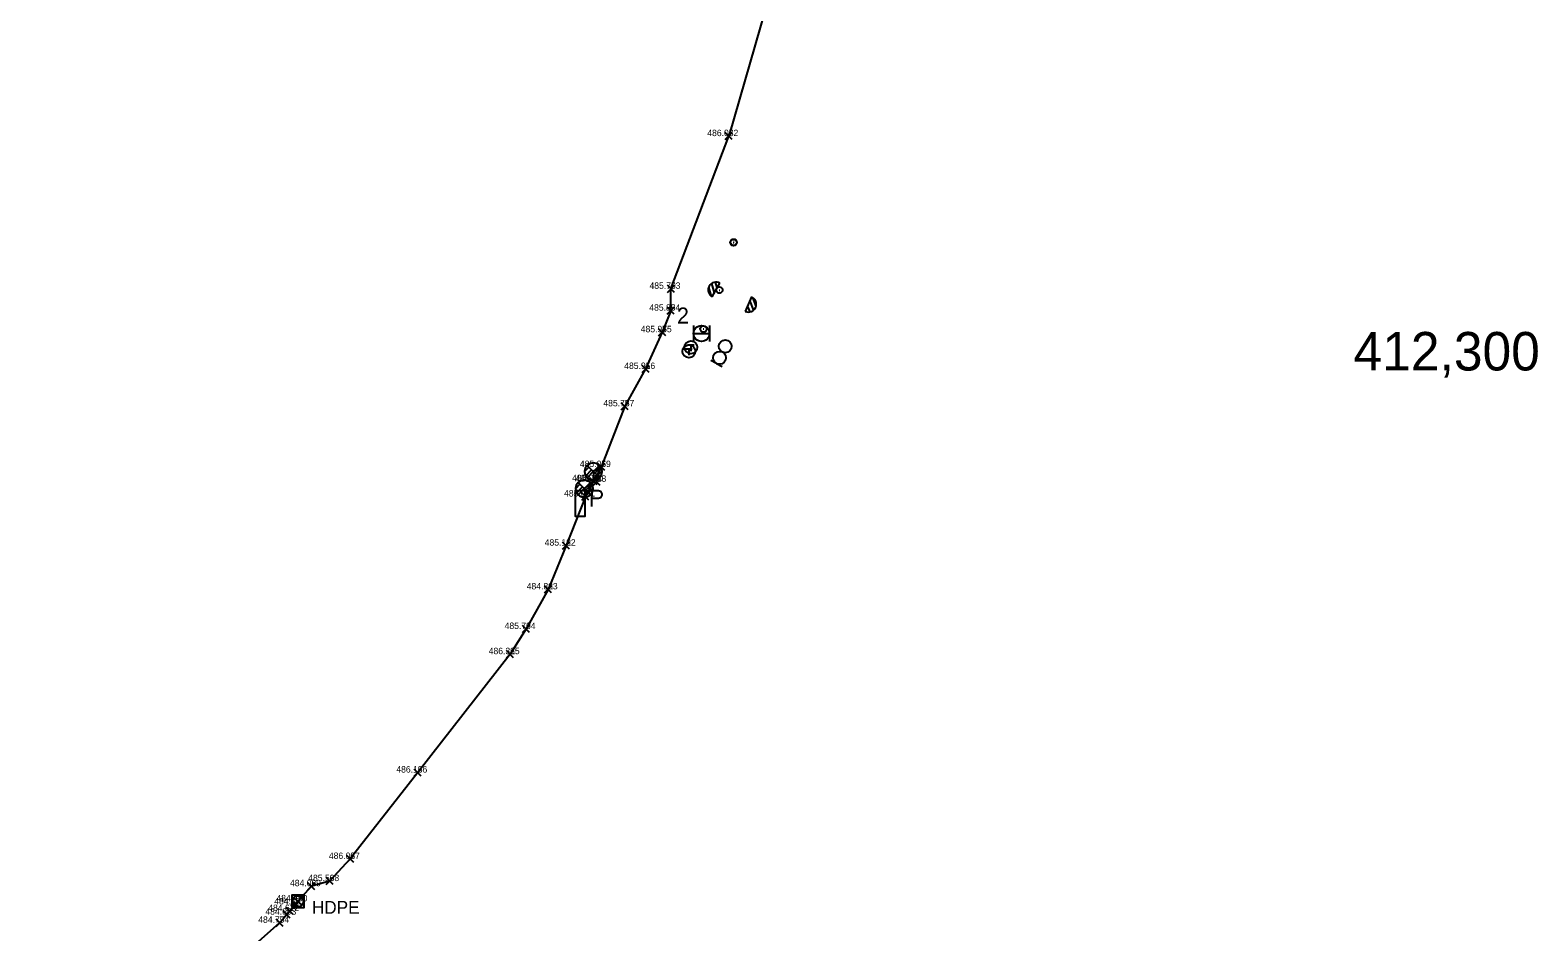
# Model space of a CAD drawing. Extents: x -874058 to -854960, y -10531873 to -1049126.
# Drawn here: x -866673.8 to -866439.1, y -1050448 to -1050307.6 of the extents above; entities that cross this region are included whole.
import ezdxf

# ---------------------------------------------------------------- set-up
doc = ezdxf.new("R2010")
doc.units = 0
for name, color, linetype in [('Vrstva 2', 7, 'Continuous'), ('Vrstva 3', 7, 'Continuous'), ('Vrstva 30', 7, 'Continuous'), ('Vrstva 31', 7, 'Continuous'), ('Vrstva 32', 7, 'Continuous'), ('Vrstva 33', 7, 'Continuous'), ('Vrstva 50', 7, 'Continuous'), ('Vrstva 6', 7, 'Continuous'), ('Vrstva 60', 7, 'Continuous'), ('Vrstva 61', 7, 'Continuous'), ('Vrstva 7', 7, 'Continuous')]:
    doc.layers.add(name, color=color, linetype=linetype)

msp = doc.modelspace()

# ---------------------------------------------------------------- linework, layer by layer
at = {"layer": 'Vrstva 3'}
for p, q in [((-866567.7, -1050349.03), (-866568.11, -1050347.61)), ((-866567.21, -1050348.48), (-866567.63, -1050347.01)), ((-866567.56, -1050349.12), (-866566.37, -1050346.96)), ((-866566.79, -1050347.72), (-866567.05, -1050346.81)), ((-866566.37, -1050346.96), (-866566.37, -1050346.96)), ((-866566.37, -1050346.96), (-866566.37, -1050346.96)), ((-866561.45, -1050349.11), (-866562.42, -1050351.38)), ((-866561.74, -1050349.78), (-866561.17, -1050351.21)), ((-866561.31, -1050349.19), (-866560.76, -1050350.56)), ((-866562.42, -1050351.38), (-866562.42, -1050351.38)), ((-866562.42, -1050351.38), (-866562.42, -1050351.38)), ((-866562.08, -1050350.59), (-866561.73, -1050351.46)), ((-866570.48, -1050353.59), (-866570.48, -1050356.05)), ((-866568.02, -1050353.59), (-866568.02, -1050356.05)), ((-866571.4, -1050356.56), (-866570.4, -1050356.56)), ((-866570.9, -1050356.56), (-866570.9, -1050357.56)), ((-866570.48, -1050354.82), (-866568.02, -1050354.82)), ((-866571.71, -1050357.2), (-866570.71, -1050357.2)), ((-866571.21, -1050357.2), (-866571.21, -1050358.2))]:
    msp.add_line(p, q, dxfattribs=at)
for centre, radius in [((-866569.25, -1050354.82), 1.23), ((-866571.21, -1050357.6), 1), ((-866570.9, -1050356.96), 1)]:
    msp.add_circle(centre, radius, dxfattribs=at)
for centre, start, end in [((-866566.96, -1050348.04), 150.9842, 240.9842), ((-866566.96, -1050348.04), 60.9842, 150.9784), ((-866561.94, -1050350.25), 336.7737, 66.7737), ((-866561.94, -1050350.25), 246.7737, 336.7679)]:
    msp.add_arc(centre, 1.23, start, end, dxfattribs=at)
at = {"layer": 'Vrstva 30'}
msp.add_lwpolyline([(-866633.04, -1050444.23), (-866631.12, -1050444.23), (-866631.12, -1050442.31), (-866633.04, -1050442.31)], close=True, dxfattribs=at)
msp.add_circle((-866632.08, -1050443.27), 0.864, dxfattribs=at)
at = {"layer": 'Vrstva 31'}
for p, q in [((-866587.44, -1050376.33), (-866586.76, -1050375.66)), ((-866585.86, -1050376.55), (-866584.94, -1050375.63)), ((-866585.13, -1050375.37), (-866585.13, -1050375.37)), ((-866585.13, -1050375.37), (-866585.13, -1050375.37)), ((-866587.27, -1050376.98), (-866586.36, -1050376.06)), ((-866587.26, -1050379.2), (-866586.34, -1050378.28)), ((-866587.05, -1050377.28), (-866587.05, -1050377.28)), ((-866587.05, -1050377.28), (-866587.05, -1050377.28)), ((-866586.53, -1050378.02), (-866586.53, -1050378.02)), ((-866586.53, -1050378.02), (-866586.53, -1050378.02)), ((-866585.45, -1050376.96), (-866584.74, -1050376.25)), ((-866585.12, -1050377.28), (-866585.12, -1050377.28)), ((-866588.83, -1050378.98), (-866588.16, -1050378.31)), ((-866588.67, -1050379.63), (-866587.76, -1050378.71)), ((-866588.45, -1050379.93), (-866588.45, -1050379.93)), ((-866588.45, -1050379.93), (-866588.45, -1050379.93)), ((-866586.85, -1050379.6), (-866586.14, -1050378.9)), ((-866586.53, -1050379.93), (-866586.53, -1050379.93))]:
    msp.add_line(p, q, dxfattribs=at)
for points in [[(-866587.04, -1050375.37), (-866586.09, -1050376.33), (-866587.05, -1050377.28)], [(-866585.13, -1050375.37), (-866586.08, -1050376.33), (-866585.12, -1050377.28)], [(-866588.44, -1050378.02), (-866587.49, -1050378.98), (-866588.45, -1050379.93)], [(-866586.53, -1050378.02), (-866587.48, -1050378.98), (-866586.53, -1050379.93)]]:
    msp.add_lwpolyline(points, dxfattribs=at)
for centre, start, end in [((-866586.09, -1050376.33), 134.5239, 224.7609), ((-866586.08, -1050376.33), 45.4761, 134.8422), ((-866586.08, -1050376.33), 315.2391, 45.4761), ((-866587.49, -1050378.98), 134.5239, 224.7609), ((-866587.48, -1050378.98), 45.4761, 134.8422), ((-866586.09, -1050376.33), 224.7623, 315.5517), ((-866587.48, -1050378.98), 315.2391, 45.4761), ((-866587.49, -1050378.98), 224.7623, 315.5517)]:
    msp.add_arc(centre, 1.35, start, end, dxfattribs=at)
at = {"layer": 'Vrstva 32'}
for points in [[(-866550.16, -1050258.3), (-866551.67, -1050267.94), (-866551.95, -1050270.2), (-866553.16, -1050280.04), (-866558.06, -1050297.61), (-866559.25, -1050304.08), (-866565.01, -1050324.07)], [(-866574.04, -1050351.27), (-866574.01, -1050347.86), (-866565.01, -1050324.07)], [(-866574.04, -1050351.27), (-866575.37, -1050354.62), (-866577.94, -1050360.34), (-866581.19, -1050366.16), (-866584.85, -1050375.62)], [(-866584.85, -1050375.62), (-866586.06, -1050377.83), (-866587.31, -1050380.21), (-866590.32, -1050387.86), (-866593.12, -1050394.68), (-866596.56, -1050400.84), (-866599.04, -1050404.77), (-866613.42, -1050423.21), (-866623.92, -1050436.67), (-866627.13, -1050440.12), (-866629.97, -1050440.92), (-866632.08, -1050443.27)], [(-866584.85, -1050375.62), (-866586.05, -1050376.28), (-866586.06, -1050377.83), (-866587.46, -1050378.89), (-866587.31, -1050380.21)], [(-866673.75, -1050481.26), (-866665.49, -1050475.11), (-866653.83, -1050464.38), (-866638.62, -1050449.9), (-866634.91, -1050446.62), (-866633.81, -1050445.36), (-866633.36, -1050444.78), (-866632.42, -1050443.75), (-866632.08, -1050443.27)]]:
    msp.add_lwpolyline(points, dxfattribs=at)
at = {"layer": 'Vrstva 33'}
msp.add_lwpolyline([(-866588.87, -1050379.28), (-866587.38, -1050379.28), (-866587.38, -1050383.31), (-866588.87, -1050383.31)], close=True, dxfattribs=at)
for points in [[(-866586.33, -1050381.78), (-866586.33, -1050379.27)], [(-866586.33, -1050379.27), (-866585.29, -1050379.27)], [(-866585.29, -1050380.51), (-866586.33, -1050380.51)], [(-866585.29, -1050379.27), (-866584.97, -1050379.37), (-866584.75, -1050379.78), (-866584.75, -1050380), (-866584.97, -1050380.42), (-866585.29, -1050380.51)]]:
    msp.add_lwpolyline(points, dxfattribs=at)
at = {"layer": 'Vrstva 50'}
for p, q in [((-866566.51, -1050348.05), (-866566.41, -1050348.05)), ((-866568.98, -1050354.11), (-866568.88, -1050354.11))]:
    msp.add_line(p, q, dxfattribs=at)
for centre in [(-866566.46, -1050348.05), (-866568.93, -1050354.11)]:
    msp.add_circle(centre, 0.5, dxfattribs=at)
at = {"layer": 'Vrstva 6'}
for q in [(-866567.78, -1050359.04), (-866566, -1050359.94)]:
    msp.add_line((-866566.89, -1050359.49), q, dxfattribs=at)
for centre in [(-866565.55, -1050356.81), (-866566.44, -1050358.6)]:
    msp.add_circle(centre, 1, dxfattribs=at)
at = {"layer": 'Vrstva 60'}
for p, q in [((-866565.56, -1050324.62), (-866564.46, -1050323.52)), ((-866564.46, -1050324.62), (-866565.56, -1050323.52)), ((-866574.56, -1050348.41), (-866573.46, -1050347.31)), ((-866573.46, -1050348.41), (-866574.56, -1050347.31)), ((-866574.59, -1050351.82), (-866573.49, -1050350.72)), ((-866573.49, -1050351.82), (-866574.59, -1050350.72)), ((-866575.92, -1050355.17), (-866574.82, -1050354.07)), ((-866574.82, -1050355.17), (-866575.92, -1050354.07)), ((-866578.49, -1050360.89), (-866577.39, -1050359.79)), ((-866577.39, -1050360.89), (-866578.49, -1050359.79)), ((-866581.74, -1050366.71), (-866580.64, -1050365.61)), ((-866580.64, -1050366.71), (-866581.74, -1050365.61)), ((-866585.4, -1050376.17), (-866584.3, -1050375.07)), ((-866584.3, -1050376.17), (-866585.4, -1050375.07)), ((-866586.61, -1050378.38), (-866585.51, -1050377.28)), ((-866585.51, -1050378.38), (-866586.61, -1050377.28)), ((-866586.11, -1050378.47), (-866585.01, -1050377.37)), ((-866585.01, -1050378.47), (-866586.11, -1050377.37)), ((-866587.86, -1050380.76), (-866586.76, -1050379.66)), ((-866586.76, -1050380.76), (-866587.86, -1050379.66)), ((-866590.87, -1050388.41), (-866589.77, -1050387.31)), ((-866589.77, -1050388.41), (-866590.87, -1050387.31)), ((-866593.67, -1050395.23), (-866592.57, -1050394.13)), ((-866592.57, -1050395.23), (-866593.67, -1050394.13)), ((-866597.11, -1050401.39), (-866596.01, -1050400.29)), ((-866596.01, -1050401.39), (-866597.11, -1050400.29)), ((-866599.59, -1050405.32), (-866598.49, -1050404.22)), ((-866598.49, -1050405.32), (-866599.59, -1050404.22)), ((-866613.97, -1050423.76), (-866612.87, -1050422.66)), ((-866612.87, -1050423.76), (-866613.97, -1050422.66)), ((-866624.47, -1050437.22), (-866623.37, -1050436.12)), ((-866623.37, -1050437.22), (-866624.47, -1050436.12)), ((-866630.52, -1050441.47), (-866629.42, -1050440.37)), ((-866629.42, -1050441.47), (-866630.52, -1050440.37)), ((-866627.68, -1050440.67), (-866626.58, -1050439.57)), ((-866626.58, -1050440.67), (-866627.68, -1050439.57)), ((-866632.97, -1050444.3), (-866631.87, -1050443.2)), ((-866631.87, -1050444.3), (-866632.97, -1050443.2)), ((-866632.63, -1050443.82), (-866631.53, -1050442.72)), ((-866631.53, -1050443.82), (-866632.63, -1050442.72)), ((-866635.46, -1050447.17), (-866634.36, -1050446.07)), ((-866634.36, -1050447.17), (-866635.46, -1050446.07)), ((-866634.36, -1050445.91), (-866633.26, -1050444.81)), ((-866633.26, -1050445.91), (-866634.36, -1050444.81)), ((-866633.91, -1050445.33), (-866632.81, -1050444.23)), ((-866632.81, -1050445.33), (-866633.91, -1050444.23))]:
    msp.add_line(p, q, dxfattribs=at)
at = {"layer": 'Vrstva 7'}
for p, q in [((-866564.31, -1050340.65), (-866564.21, -1050340.65)), ((-866564.28, -1050340.6), (-866564.18, -1050340.6))]:
    msp.add_line(p, q, dxfattribs=at)
for centre in [(-866564.26, -1050340.65), (-866564.23, -1050340.6)]:
    msp.add_circle(centre, 0.5, dxfattribs=at)

# ---------------------------------------------------------------- texts
at = {"layer": 'Vrstva 2'}
msp.add_text('2', height=2.5, dxfattribs=at).set_placement((-866573.06, -1050353.27))
at = {"layer": 'Vrstva 32'}
msp.add_text('HDPE', height=2, dxfattribs=at).set_placement((-866629.9, -1050445.21))
at = {"layer": 'Vrstva 60'}
for s, p in [('52', (-866565.01, -1050324.07)), ('53', (-866574.01, -1050347.86)), ('54', (-866574.04, -1050351.27)), ('55', (-866575.37, -1050354.62)), ('56', (-866577.94, -1050360.34)), ('57', (-866581.19, -1050366.16)), ('59', (-866584.85, -1050375.62)), ('60', (-866586.06, -1050377.83)), ('58', (-866585.56, -1050377.92)), ('61', (-866587.31, -1050380.21)), ('62', (-866590.32, -1050387.86)), ('63', (-866593.12, -1050394.68)), ('64', (-866596.56, -1050400.84)), ('65', (-866599.04, -1050404.77)), ('66', (-866613.42, -1050423.21)), ('67', (-866623.92, -1050436.67)), ('68', (-866627.13, -1050440.12)), ('69', (-866629.97, -1050440.92)), ('72', (-866633.36, -1050444.78)), ('71', (-866632.42, -1050443.75)), ('70', (-866632.08, -1050443.27)), ('74', (-866634.91, -1050446.62)), ('73', (-866633.81, -1050445.36))]:
    msp.add_text(s, height=1, dxfattribs=at).set_placement(p)
at = {"layer": 'Vrstva 61'}
for s, p in [('486.08 ', (-866568.34, -1050324.07)), ('485.70 ', (-866577.34, -1050347.86)), ('485.89 ', (-866577.37, -1050351.27)), ('485.97 ', (-866578.7, -1050354.62)), ('485.91 ', (-866581.27, -1050360.34)), ('485.78 ', (-866584.52, -1050366.16)), ('485.06 ', (-866588.18, -1050375.62)), ('485.04 ', (-866589.39, -1050377.83)), ('485.91 ', (-866588.89, -1050377.92)), ('485.00 ', (-866590.64, -1050380.21)), ('485.12 ', (-866593.65, -1050387.86)), ('484.82 ', (-866596.45, -1050394.68)), ('485.79 ', (-866599.89, -1050400.84)), ('486.32 ', (-866602.37, -1050404.77)), ('486.18 ', (-866616.75, -1050423.21)), ('486.08 ', (-866627.25, -1050436.67)), ('485.59 ', (-866630.46, -1050440.12)), ('484.08 ', (-866633.3, -1050440.92)), ('484.61 ', (-866636.69, -1050444.78)), ('484.53 ', (-866635.75, -1050443.75)), ('484.45 ', (-866635.41, -1050443.27)), ('484.79 ', (-866638.24, -1050446.62)), ('484.69 ', (-866637.14, -1050445.36))]:
    msp.add_text(s, height=1, dxfattribs=at).set_placement(p)
at = {"layer": 'Vrstva 7'}
msp.add_text('412,300', height=6, dxfattribs=at).set_placement((-866467.74, -1050360.58))

doc.saveas('drawing.dxf')
